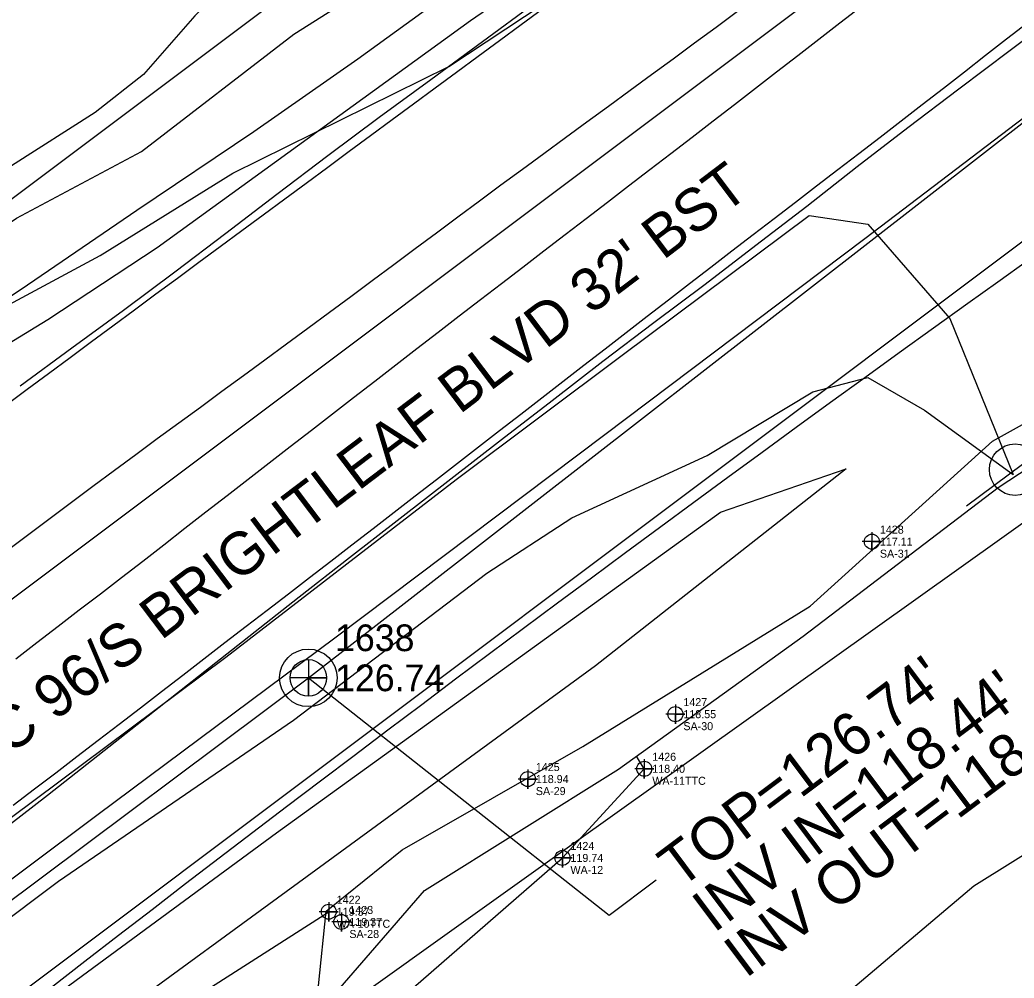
# Model space of a CAD drawing. Extents: x 2186615 to 2188822, y 629899 to 631820.
# Drawn here: x 2187253.2 to 2187346.4, y 630429.6 to 630519.4 of the extents above; entities that cross this region are included whole.
import ezdxf

# ---------------------------------------------------------------- set-up
doc = ezdxf.new("R2010")
doc.units = 0
for name, color, linetype in [('Exist Environmental Wetland Boundary', 7, 'Continuous'), ('Exist Environmental Wetland Boundary Cogo Comment', 7, 'Continuous'), ('Exist Environmental Wetland Boundary Cogo Elevation', 7, 'Continuous'), ('Exist Environmental Wetland Boundary Cogo Number', 7, 'Continuous'), ('Exist Environmental Wetland Boundary Cogo Point CELL', 7, 'Continuous'), ('Exist Guardrail', 7, 'Continuous'), ('Exist Horizontal Alignment', 7, 'Continuous'), ('Exist Hydro Jurisdictional Stream or Body of Water', 7, 'Continuous'), ('Exist Right of Way Line', 7, 'Continuous'), ('Exist Roads EOP', 7, 'Continuous'), ('Exist Roads EOP Text', 7, 'Continuous'), ('Exist Roads EOT', 7, 'Continuous'), ('Exist Utilities Gas UG Line SUE LOS B', 7, 'Continuous'), ('Exist Utilities Sanitary Sewer Manhole CELL', 7, 'Continuous'), ('Exist Utilities Sanitary Sewer Manhole Cogo Elevation', 7, 'Continuous'), ('Exist Utilities Sanitary Sewer Manhole Cogo Number', 7, 'Continuous'), ('Exist Utilities Sanitary Sewer Manhole Leader', 7, 'Continuous'), ('Exist Utilities Sanitary Sewer Manhole Top Elevation', 7, 'Continuous'), ('Exist Utilities Sanitary Sewer UG Line', 7, 'Continuous'), ('Exist Utilities Sanitary Sewer UG Line Invert Elevation', 7, 'Continuous'), ('Exist Utilities Telephone Pole CELL', 7, 'Continuous'), ('Exist Utilities Telephone UG Cable SUE LOS C', 7, 'Continuous'), ('Exist Utilities Telephone UG FO SUE LOS B', 7, 'Continuous'), ('Exist Utilities Water UG Line SUE LOS B', 7, 'Continuous'), ('Exist Vegetation Hedge Row', 7, 'Continuous'), ('Exist Vegetation Woods Line', 7, 'Continuous')]:
    doc.layers.add(name, color=color, linetype=linetype)

msp = doc.modelspace()

# ---------------------------------------------------------------- linework, layer by layer
at = {"layer": 'Exist Environmental Wetland Boundary'}
for points in [[(2187200.333, 630357.676), (2187218.012, 630369.88), (2187243.865, 630391.755), (2187268.738, 630413.3), (2187284.769, 630424.116), (2187304.062, 630440.889), (2187311.728, 630449.237), (2187310.985, 630450.407)], [(2187091.311, 630271.672), (2187085.676, 630287.812), (2187098.271, 630306.167), (2187117.246, 630318.391), (2187145.167, 630331.818), (2187167.383, 630352.861), (2187202.427, 630381.298), (2187228.671, 630401.09), (2187258.21, 630420.516), (2187282.166, 630435.853)]]:
    msp.add_lwpolyline(points, dxfattribs=at)
at = {"layer": 'Exist Environmental Wetland Boundary Cogo Point CELL'}
for points in [[(2187333.049, 630471.403), (2187333.049, 630469.603), (2187333.049, 630470.503), (2187333.949, 630470.503), (2187332.149, 630470.503)], [(2187314.64, 630455.251), (2187314.64, 630453.451), (2187314.64, 630454.351), (2187315.54, 630454.351), (2187313.74, 630454.351)], [(2187311.728, 630450.137), (2187311.728, 630448.337), (2187311.728, 630449.237), (2187312.628, 630449.237), (2187310.828, 630449.237)], [(2187300.82, 630449.175), (2187300.82, 630447.375), (2187300.82, 630448.275), (2187301.72, 630448.275), (2187299.92, 630448.275)], [(2187304.062, 630441.789), (2187304.062, 630439.989), (2187304.062, 630440.889), (2187304.962, 630440.889), (2187303.162, 630440.889)], [(2187282.166, 630436.753), (2187282.166, 630434.953), (2187282.166, 630435.853), (2187283.066, 630435.853), (2187281.266, 630435.853)], [(2187283.35, 630435.796), (2187283.35, 630433.996), (2187283.35, 630434.896), (2187284.25, 630434.896), (2187282.45, 630434.896)]]:
    msp.add_lwpolyline(points, dxfattribs=at)
for centre in [(2187333.049, 630470.503), (2187314.64, 630454.351), (2187311.728, 630449.237), (2187300.82, 630448.275), (2187304.062, 630440.889), (2187282.166, 630435.853), (2187283.35, 630434.896)]:
    msp.add_circle(centre, 0.703, dxfattribs=at)
at = {"layer": 'Exist Guardrail'}
for points in [[(2187241.55, 630486.346), (2187253.35, 630494.155), (2187264.205, 630501.541), (2187275.163, 630508.92), (2187284.892, 630515.715), (2187294.523, 630522.691), (2187305.629, 630530.633), (2187316.311, 630538.47), (2187330.339, 630548.737), (2187345.501, 630559.821), (2187361.866, 630571.876), (2187380.98, 630586.026), (2187387.099, 630590.708), (2187395.301, 630597.179), (2187406.457, 630605.967), (2187415.255, 630612.832), (2187425.741, 630621.13)], [(2187434.115, 630575.844), (2187413.642, 630560.327), (2187392.389, 630544.34), (2187371.189, 630528.329), (2187353.022, 630514.54), (2187332.378, 630498.862), (2187308.035, 630480.517), (2187282.875, 630461.57), (2187260.432, 630444.878), (2187240.787, 630430.164), (2187221.99, 630416.084), (2187199.867, 630399.404), (2187178.435, 630383.307), (2187159.654, 630369.054), (2187143.316, 630356.53), (2187128.809, 630345.412), (2187116.826, 630336.517)]]:
    msp.add_lwpolyline(points, dxfattribs=at)
at = {"layer": 'Exist Horizontal Alignment'}
msp.add_line((2187136.406, 630378.107), (2188520.855, 631416.042), dxfattribs=at)
at = {"layer": 'Exist Hydro Jurisdictional Stream or Body of Water'}
for points in [[(2187197.322, 630361.43), (2187213.945, 630373.562), (2187222.659, 630386.877), (2187241.705, 630395.38), (2187246.836, 630403.358), (2187255.086, 630412.327), (2187267.186, 630417.823), (2187275.409, 630422.294), (2187281.209, 630428.913), (2187281.92, 630435.898), (2187289.055, 630441.644), (2187305.984, 630451.32), (2187327.255, 630464.456), (2187344.34, 630479.914), (2187359.178, 630488.147), (2187368.792, 630495.674), (2187384.724, 630510.856), (2187399.768, 630521.857), (2187428.248, 630541.272), (2187449.565, 630557.041)], [(2187200.333, 630357.676), (2187217.66, 630373.541), (2187219.417, 630375.085), (2187222.068, 630380.972), (2187226.921, 630384.519), (2187239.946, 630392.223), (2187243.455, 630393.717), (2187246.058, 630398.658), (2187250.235, 630404.156), (2187257.633, 630410.563), (2187272.327, 630417.422), (2187280.629, 630425.711), (2187291.154, 630437.828), (2187309.311, 630449.202), (2187326.618, 630461.663), (2187344.871, 630475.57), (2187361.058, 630486.179), (2187383.779, 630505.824), (2187403.688, 630519.913), (2187435.685, 630540.516), (2187447.835, 630554.369)]]:
    msp.add_lwpolyline(points, dxfattribs=at)
at = {"layer": 'Exist Right of Way Line'}
for p, q in [((2187118.411, 630402.11), (2188502.827, 631440.021)), ((2187154.402, 630354.104), (2188538.851, 631392.039))]:
    msp.add_line(p, q, dxfattribs=at)
for centre, radius, start, end in [((2191071.837, 625294.065), 6398.299, 123.691884, 125.6572198), ((2189028.8, 628141.736), 2893.554, 125.65722, 135.708207)]:
    msp.add_arc(centre, radius, start, end, dxfattribs=at)
at = {"layer": 'Exist Roads EOP'}
for points in [[(2187253.251, 630485.092), (2187258.089, 630488.64), (2187262.927, 630492.187), (2187267.738, 630495.773), (2187272.517, 630499.4), (2187277.296, 630503.028), (2187282.075, 630506.656), (2187286.886, 630510.241), (2187291.726, 630513.787), (2187296.566, 630517.333), (2187301.404, 630520.881), (2187306.229, 630524.448), (2187311.052, 630528.017), (2187315.874, 630531.586), (2187320.697, 630535.155), (2187325.509, 630538.739), (2187330.275, 630542.382), (2187335.039, 630546.03), (2187339.802, 630549.678), (2187344.565, 630553.327), (2187349.328, 630556.974)], [(2187350.794, 630520.088), (2187345.995, 630516.487), (2187341.2, 630512.881), (2187336.416, 630509.26), (2187331.67, 630505.589), (2187326.946, 630501.89), (2187322.19, 630498.233), (2187317.423, 630494.59), (2187312.632, 630490.978), (2187307.849, 630487.355), (2187303.09, 630483.702), (2187298.352, 630480.022), (2187293.613, 630476.343), (2187288.87, 630472.67), (2187284.124, 630468.999), (2187279.391, 630465.313), (2187274.679, 630461.598), (2187269.968, 630457.883), (2187265.258, 630454.167), (2187260.547, 630450.451), (2187255.836, 630446.736), (2187251.071, 630443.09)]]:
    msp.add_lwpolyline(points, dxfattribs=at)
at = {"layer": 'Exist Roads EOT'}
for points in [[(2187251.908, 630483.289), (2187253.918, 630484.775), (2187255.928, 630486.262), (2187257.938, 630487.748), (2187259.947, 630489.235), (2187261.957, 630490.721), (2187263.967, 630492.208), (2187265.978, 630493.694), (2187267.989, 630495.179), (2187270, 630496.663), (2187272.012, 630498.147), (2187274.024, 630499.631), (2187276.036, 630501.114), (2187278.048, 630502.598), (2187280.06, 630504.082), (2187282.072, 630505.566), (2187284.084, 630507.05), (2187286.096, 630508.533), (2187288.108, 630510.017), (2187290.12, 630511.501), (2187292.132, 630512.985), (2187294.144, 630514.469), (2187296.156, 630515.953), (2187298.168, 630517.437), (2187300.18, 630518.92), (2187302.192, 630520.404)], [(2187252.065, 630469.708), (2187254.073, 630471.198), (2187256.079, 630472.69), (2187258.08, 630474.187), (2187260.081, 630475.686), (2187262.085, 630477.181), (2187264.095, 630478.667), (2187266.109, 630480.147), (2187268.125, 630481.625), (2187270.143, 630483.102), (2187272.16, 630484.578), (2187274.177, 630486.054), (2187276.193, 630487.533), (2187278.207, 630489.014), (2187280.219, 630490.498), (2187282.229, 630491.984), (2187284.239, 630493.471), (2187286.247, 630494.959), (2187288.255, 630496.449), (2187290.262, 630497.939), (2187292.269, 630499.43), (2187294.275, 630500.921), (2187296.282, 630502.412), (2187298.29, 630503.901), (2187300.305, 630505.38), (2187302.322, 630506.857), (2187304.339, 630508.334), (2187306.357, 630509.811), (2187308.374, 630511.287), (2187310.391, 630512.764), (2187312.408, 630514.241), (2187314.425, 630515.718), (2187316.44, 630517.197), (2187318.453, 630518.68), (2187320.465, 630520.164)], [(2187252.855, 630459.538), (2187254.837, 630461.061), (2187256.819, 630462.585), (2187258.801, 630464.108), (2187260.782, 630465.632), (2187262.762, 630467.159), (2187264.739, 630468.688), (2187266.715, 630470.219), (2187268.691, 630471.751), (2187270.667, 630473.282), (2187272.643, 630474.813), (2187274.618, 630476.345), (2187276.594, 630477.876), (2187278.57, 630479.408), (2187280.546, 630480.939), (2187282.522, 630482.47), (2187284.498, 630484.002), (2187286.474, 630485.533), (2187288.45, 630487.064), (2187290.427, 630488.594), (2187292.408, 630490.119), (2187294.391, 630491.641), (2187296.374, 630493.162), (2187298.358, 630494.684), (2187300.342, 630496.205), (2187302.326, 630497.726), (2187304.31, 630499.247), (2187306.293, 630500.769), (2187308.277, 630502.29), (2187310.261, 630503.811), (2187312.244, 630505.333), (2187314.226, 630506.857), (2187316.206, 630508.384), (2187318.185, 630509.911), (2187320.164, 630511.438), (2187322.144, 630512.964), (2187324.123, 630514.491), (2187326.103, 630516.018), (2187328.082, 630517.545), (2187330.061, 630519.072), (2187332.041, 630520.599)], [(2187347.646, 630519.069), (2187345.67, 630517.537), (2187343.694, 630516.006), (2187341.718, 630514.475), (2187339.742, 630512.943), (2187337.766, 630511.412), (2187335.789, 630509.881), (2187333.813, 630508.35), (2187331.833, 630506.824), (2187329.85, 630505.302), (2187327.866, 630503.781), (2187325.882, 630502.26), (2187323.898, 630500.739), (2187321.914, 630499.217), (2187319.93, 630497.696), (2187317.947, 630496.175), (2187315.963, 630494.654), (2187313.983, 630493.128), (2187312.006, 630491.598), (2187310.03, 630490.066), (2187308.054, 630488.535), (2187306.079, 630487.003), (2187304.103, 630485.471), (2187302.127, 630483.94), (2187300.152, 630482.408), (2187298.176, 630480.876), (2187296.201, 630479.345), (2187294.225, 630477.813), (2187292.249, 630476.281), (2187290.274, 630474.75), (2187288.298, 630473.219), (2187286.319, 630471.691), (2187284.338, 630470.166), (2187282.356, 630468.642), (2187280.374, 630467.119), (2187278.393, 630465.595), (2187276.411, 630464.072), (2187274.429, 630462.548), (2187272.447, 630461.024), (2187270.466, 630459.5), (2187268.485, 630457.975), (2187266.504, 630456.45), (2187264.525, 630454.924), (2187262.544, 630453.399), (2187260.561, 630451.877), (2187258.575, 630450.358), (2187256.589, 630448.839), (2187254.602, 630447.322), (2187252.616, 630445.804)]]:
    msp.add_lwpolyline(points, dxfattribs=at)
at = {"layer": 'Exist Utilities Gas UG Line SUE LOS B'}
msp.add_lwpolyline([(2187126.474, 630392.391), (2187146.749, 630408.061), (2187165.948, 630422.166), (2187183.003, 630435.52), (2187198.842, 630447.531), (2187220.79, 630463.611), (2187230.742, 630480.093), (2187238.842, 630491.282), (2187252.932, 630500.782), (2187264.616, 630507.024), (2187278.901, 630518.022), (2187291.156, 630525.789), (2187304.759, 630536.934), (2187314.395, 630544.202), (2187331.496, 630558.331), (2187350.478, 630574.64)], dxfattribs=at)
at = {"layer": 'Exist Utilities Sanitary Sewer Manhole CELL'}
msp.add_lwpolyline([(2187280.261, 630459.464), (2187280.261, 630456.039), (2187280.261, 630457.751), (2187281.973, 630457.751), (2187278.549, 630457.751)], dxfattribs=at)
for radius in [2.694, 1.712]:
    msp.add_circle((2187280.261, 630457.751), radius, dxfattribs=at)
at = {"layer": 'Exist Utilities Sanitary Sewer Manhole Leader'}
msp.add_lwpolyline([(2187280.261, 630457.751), (2187308.432, 630435.54), (2187312.832, 630438.838)], dxfattribs=at)
at = {"layer": 'Exist Utilities Sanitary Sewer UG Line'}
for p, q in [((2187280.261, 630457.751), (2187438.759, 630580.85)), ((2186953.526, 630213.342), (2187280.261, 630457.751))]:
    msp.add_line(p, q, dxfattribs=at)
at = {"layer": 'Exist Utilities Telephone Pole CELL'}
msp.add_line((2187341.922, 630473.843), (2187350.998, 630480.638), dxfattribs=at)
msp.add_circle((2187346.465, 630477.244), 2.407, dxfattribs=at)
at = {"layer": 'Exist Utilities Telephone UG Cable SUE LOS C'}
msp.add_lwpolyline([(2187048.711, 630267.562), (2187045.354, 630278.254), (2187057.018, 630287.248), (2187078.192, 630303.416), (2187102.037, 630322.514), (2187119.945, 630336.137), (2187137.937, 630349.883), (2187161.709, 630367.862), (2187186.024, 630384.639), (2187207.077, 630401.804), (2187231.599, 630419.787), (2187256.848, 630438.711), (2187278.852, 630453.798), (2187296.978, 630467.542), (2187304.942, 630472.732), (2187317.617, 630478.554), (2187327.51, 630484.53), (2187332.683, 630485.862), (2187337.992, 630482.804), (2187346.28, 630476.796)], dxfattribs=at)
at = {"layer": 'Exist Utilities Telephone UG FO SUE LOS B'}
for points in [[(2187221.787, 630477.44), (2187244.494, 630488.549), (2187260.766, 630497.303), (2187273.174, 630505.002), (2187293.431, 630514.995), (2187319.925, 630532.538), (2187378.478, 630575.929), (2187483.974, 630656.576), (2187503.962, 630671.26), (2187608.063, 630745.856)], [(2187049.385, 630270.146), (2187042.504, 630278.367), (2187044.061, 630284.337), (2187057.315, 630294.022), (2187075.644, 630307.116), (2187098.729, 630326.668), (2187116.947, 630341.492), (2187134.442, 630355.423), (2187157.809, 630373.051), (2187181.899, 630390.785), (2187205.122, 630408.701), (2187231.973, 630429.319), (2187252.444, 630444.703), (2187272.54, 630459.689), (2187294.094, 630476.316), (2187309.645, 630487.965), (2187327.188, 630501.034), (2187332.668, 630500.224), (2187340.344, 630491.389), (2187346.28, 630476.796)]]:
    msp.add_lwpolyline(points, dxfattribs=at)
at = {"layer": 'Exist Utilities Water UG Line SUE LOS B'}
msp.add_lwpolyline([(2187188.37, 630443.024), (2187206.689, 630458.058), (2187226.474, 630471.999), (2187238.766, 630480.882), (2187255.867, 630491.296), (2187266.081, 630498.059), (2187295.46, 630519.284), (2187306.869, 630527.171), (2187321.342, 630537.501), (2187340.106, 630551.443), (2187356.85, 630563.988), (2187378.548, 630580.267)], dxfattribs=at)
at = {"layer": 'Exist Vegetation Hedge Row'}
msp.add_lwpolyline([(2187300.929, 630562.484), (2187306.827, 630558.442), (2187308.329, 630555.745), (2187308.601, 630551.641), (2187307.631, 630549.109), (2187305.892, 630548.006), (2187302.34, 630548.066), (2187299.032, 630546.426), (2187297.353, 630542.227), (2187294.333, 630539.009), (2187290.065, 630535.596), (2187284.36, 630533.382), (2187279.853, 630531.121), (2187277.082, 630527.469), (2187269.632, 630519.747), (2187264.825, 630514.256), (2187260.302, 630510.672), (2187252.455, 630505.696)], dxfattribs=at)
at = {"layer": 'Exist Vegetation Woods Line'}
for points in [[(2187105.726, 630299.086), (2187150.799, 630331.829), (2187206.105, 630372.034), (2187256.074, 630407.258), (2187300.913, 630439.289), (2187349.475, 630473.877), (2187396.874, 630507.865), (2187440.691, 630538.214), (2187466.075, 630555.071), (2187474.722, 630557.755), (2187481.166, 630558.923), (2187486.051, 630559.676), (2187489.303, 630561.136), (2187491.384, 630563.953), (2187492.451, 630570.166), (2187494.251, 630572.315)], [(2187473.569, 630527.3), (2187453.75, 630512.916), (2187435.186, 630501.319), (2187410.074, 630490.236), (2187391.303, 630473.708), (2187377.298, 630457.794), (2187368.165, 630449.57), (2187357.71, 630447.66), (2187342.586, 630438.232), (2187325.212, 630423.547), (2187317.288, 630416.779), (2187299.412, 630410.909), (2187286.374, 630395.698), (2187276.981, 630383.819), (2187255.826, 630368.846), (2187238.494, 630356.985), (2187221.565, 630339.526), (2187197.373, 630321.295), (2187174.715, 630306.11), (2187151.591, 630284.746), (2187135.361, 630271.561)], [(2187230.496, 630408.889), (2187277.266, 630443.245), (2187318.865, 630473.262), (2187330.634, 630477.313), (2187307.147, 630458.864), (2187234.208, 630405.639), (2187193.004, 630375.627), (2187170.079, 630359.227), (2187132.552, 630332.436), (2187105.521, 630312.125)]]:
    msp.add_lwpolyline(points, dxfattribs=at)

# ---------------------------------------------------------------- texts
at = {"layer": 'Exist Environmental Wetland Boundary Cogo Comment'}
for s, p in [('SA-31', (2187333.799, 630469.003)), ('SA-30', (2187315.39, 630452.851)), ('WA-11TTC', (2187312.478, 630447.737)), ('SA-29', (2187301.57, 630446.775)), ('WA-12', (2187304.812, 630439.389)), ('WA-10TTC', (2187282.916, 630434.353)), ('SA-28', (2187284.1, 630433.396))]:
    msp.add_text(s, height=0.75, dxfattribs=at).set_placement(p)
at = {"layer": 'Exist Environmental Wetland Boundary Cogo Elevation'}
for s, p in [('117.11', (2187333.799, 630470.128)), ('118.55', (2187315.39, 630453.976)), ('118.40', (2187312.478, 630448.862)), ('118.94', (2187301.57, 630447.9)), ('119.74', (2187304.812, 630440.514)), ('119.37', (2187282.916, 630435.478)), ('119.37', (2187284.1, 630434.521))]:
    msp.add_text(s, height=0.75, dxfattribs=at).set_placement(p)
at = {"layer": 'Exist Environmental Wetland Boundary Cogo Number'}
for s, p in [('1428', (2187333.799, 630471.253)), ('1427', (2187315.39, 630455.101)), ('1426', (2187312.478, 630449.987)), ('1425', (2187301.57, 630449.025)), ('1424', (2187304.812, 630441.639)), ('1422', (2187282.916, 630436.603)), ('1423', (2187284.1, 630435.646))]:
    msp.add_text(s, height=0.75, dxfattribs=at).set_placement(p)
at = {"layer": 'Exist Roads EOP Text'}
msp.add_text("US 301/NC 96/S BRIGHTLEAF BLVD 32' BST", height=4, rotation=37.12382, dxfattribs=at).set_placement((2187233.734, 630436.435))
at = {"layer": 'Exist Utilities Sanitary Sewer Manhole Cogo Elevation'}
msp.add_text('126.74', height=2.5, dxfattribs=at).set_placement((2187282.761, 630456.501))
at = {"layer": 'Exist Utilities Sanitary Sewer Manhole Cogo Number'}
msp.add_text('1638', height=2.5, dxfattribs=at).set_placement((2187282.761, 630460.251))
at = {"layer": 'Exist Utilities Sanitary Sewer Manhole Top Elevation'}
msp.add_text("TOP=126.74'", height=4, rotation=36.85926, dxfattribs=at).set_placement((2187315.046, 630437.938))
at = {"layer": 'Exist Utilities Sanitary Sewer UG Line Invert Elevation'}
for s, p in [("INV IN=118.44'", (2187318.24, 630433.8)), ("INV OUT=118.24'", (2187321.214, 630429.555))]:
    msp.add_text(s, height=4, rotation=36.85926, dxfattribs=at).set_placement(p)

doc.saveas('drawing.dxf')
